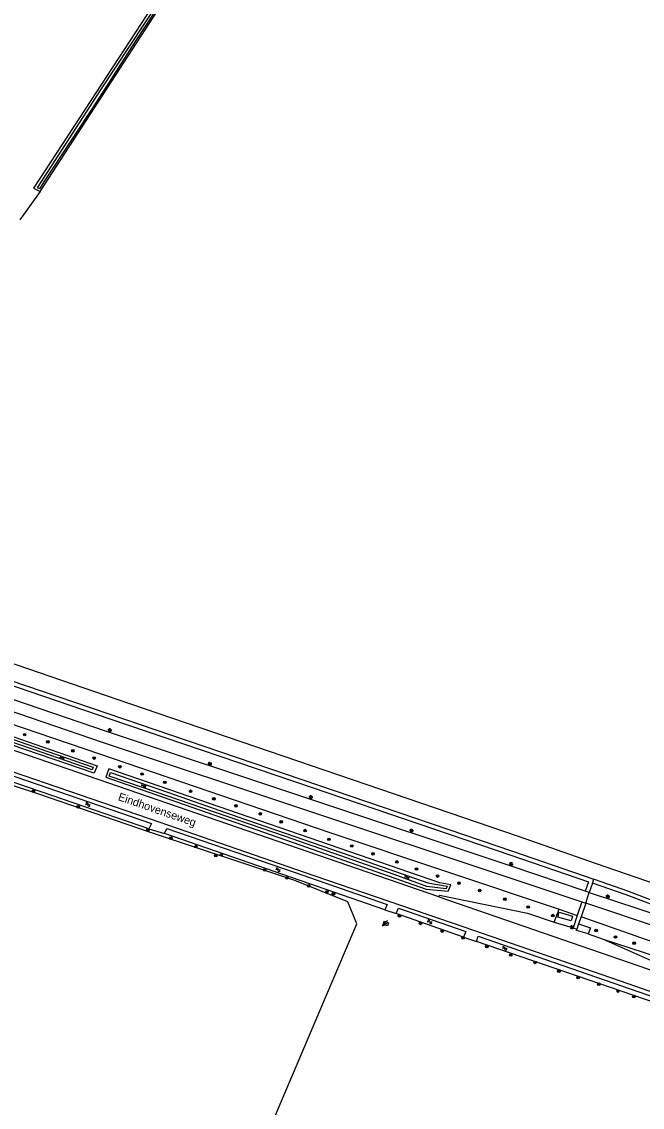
# Model space of a CAD drawing. Extents: x 135990 to 139000, y 393500 to 396000.
# Drawn here: x 136793.9 to 136987.7, y 394991 to 395330 of the extents above; entities that cross this region are included whole.
import ezdxf

# ---------------------------------------------------------------- set-up
doc = ezdxf.new("R2010")
doc.units = 0
for name, color, linetype in [('gg-afsc-faunaraster', 7, 'Continuous'), ('gg-anno-openbare ruimte label', 7, 'Continuous'), ('gg-bbg-abri', 7, 'Continuous'), ('gg-bbg-lage trafo', 7, 'Continuous'), ('gg-knt-bronhoudergrens', 7, 'Continuous'), ('gg-knt-verharding', 7, 'Continuous'), ('gg-knt-verharding nz', 7, 'Continuous'), ('gg-kntw-bovenkant insteek waterloop', 7, 'Continuous'), ('gg-kntw-waterlijn', 7, 'Continuous'), ('gt-grn-groengrens', 7, 'Continuous'), ('gt-grn-weggrens', 7, 'Continuous'), ('gt-symb-boom', 7, 'Continuous'), ('gt-symb-lichtmast', 7, 'Continuous'), ('gt-symb-trafo symbool', 7, 'Continuous'), ('gt-symb-watersymbool', 7, 'Continuous'), ('gx-grn-maaiveld', 7, 'Continuous')]:
    doc.layers.add(name, color=color, linetype=linetype)

# ---------------------------------------------------------------- blocks, each defined once
blk = doc.blocks.new('gt0-BOOM')
at = {"layer": 'gt-symb-boom'}
for radius in [0.4, 0.2]:
    blk.add_circle((0, 0), radius, dxfattribs=at)
blk = doc.blocks.new('gt0-LMAST')
at = {"layer": 'gt-symb-lichtmast'}
for p, q in [((-0.18, 0.17), (-0.45, 0.44)), ((-0.01, 0.25), (-0.01, 0.62)), ((0.17, 0.17), (0.44, 0.44)), ((-0.26, 0), (-0.63, 0)), ((-0.18, -0.18), (-0.45, -0.45)), ((-0.01, -0.25), (-0.01, -0.63)), ((0.44, -0.45), (0.17, -0.18)), ((0.24, 0), (0.62, 0))]:
    blk.add_line(p, q, dxfattribs=at)
blk.add_circle((-0.01, 0), 0.25, dxfattribs=at)
blk = doc.blocks.new('gt0-WA')
at = {"layer": 'gt-symb-watersymbool'}
for centre, start, end in [((-0.32, 0.02), 28.0725, 151.9275), ((0.43, 0.42), 208.0725, 331.9275), ((-0.32, -0.43), 28.0725, 151.9275), ((0.43, -0.03), 208.0725, 331.9275)]:
    blk.add_arc(centre, 0.425, start, end, dxfattribs=at)
blk = doc.blocks.new('gt0-HSP')
at = {"layer": 'gt-symb-trafo symbool'}
for points in [[(0.77, 0.75), (-0.53, 0), (0.47, 0), (-0.83, -0.75)], [(-0.22, -0.24), (-0.83, -0.75), (-0.08, -0.48)]]:
    blk.add_lwpolyline(points, dxfattribs=at)

msp = doc.modelspace()

# ---------------------------------------------------------------- linework, layer by layer
at = {"layer": 'gg-afsc-faunaraster'}
msp.add_lwpolyline([(136632.303, 395184.373), (136706.675, 395158.632), (136760.957, 395139.889), (136823.561, 395118.476), (136948.867, 395075.662), (136972.921, 395067.235), (136995.319, 395059.49)], dxfattribs=at)
at = {"layer": 'gg-bbg-abri'}
msp.add_lwpolyline([(136965.858, 395050.693), (136965.404, 395049.174), (136961.279, 395050.368), (136961.733, 395051.888), (136965.858, 395050.693)], dxfattribs=at)
at = {"layer": 'gg-bbg-lage trafo'}
msp.add_lwpolyline([(136907.09, 395049.068), (136908.417, 395048.605), (136908.08, 395047.639), (136906.753, 395048.102), (136907.09, 395049.068)], dxfattribs=at)
at = {"layer": 'gg-knt-bronhoudergrens'}
msp.add_line((136799.618, 395276.969), (136793.326, 395268.191), dxfattribs=at)
at = {"layer": 'gg-knt-verharding'}
for p, q in [((136972.134, 395060.996), (136971.109, 395058.053)), ((136924.147, 395056.706), (137012.655, 395026.169)), ((136960.175, 395048.76), (136961.689, 395052.865)), ((136961.689, 395052.865), (136967.364, 395050.891)), ((136968.823, 395055.089), (136967.364, 395050.891)), ((136970.056, 395054.698), (136968.573, 395050.468)), ((136967.364, 395050.891), (136966.032, 395047.06)), ((136968.573, 395050.468), (136967.738, 395048.295)), ((136966.032, 395047.06), (136967.227, 395046.629)), ((136967.738, 395048.295), (136967.227, 395046.629)), ((136970.807, 395045.091), (136975.455, 395043.512))]:
    msp.add_line(p, q, dxfattribs=at)
for points in [[(136724.247, 395146.727), (136947.105, 395070.926), (136972.554, 395062.218)], [(136725.309, 395145.037), (136758.782, 395133.671), (136821.432, 395112.332), (136884.552, 395090.872), (136946.608, 395069.724), (136970.887, 395061.4), (136969.878, 395058.479)], [(136969.878, 395058.479), (136946.693, 395066.249), (136883.58, 395087.351), (136820.389, 395108.318), (136757.753, 395129.696), (136724.034, 395141.283)], [(136725.005, 395137.127), (136819.266, 395104.948), (136882.523, 395083.915), (136945.662, 395062.844), (136968.823, 395055.089)], [(136924.147, 395056.706), (136886.334, 395069.682), (136789.614, 395103.003), (136728.373, 395124.272)], [(136726.14, 395118.098), (136787.27, 395097.063), (136837.024, 395079.972), (136885.124, 395063.406), (136931.921, 395047.31), (136980.708, 395030.491), (137010.641, 395020.085), (137020.133, 395016.766), (137027.471, 395014.486), (137030.652, 395013.873)], [(136972.554, 395062.218), (136972.603, 395062.201), (136983.062, 395058.544), (136991.512, 395055.298), (136998.208, 395052.756)], [(136997.616, 395051.522), (136991.144, 395054.108), (136982.602, 395057.304), (136972.134, 395060.996)], [(136924.147, 395056.706), (136924.327, 395057.249), (136951.786, 395051.628), (136960.175, 395048.76)], [(136971.109, 395058.053), (136994.531, 395050.331), (137002.721, 395048.173)], [(137000.991, 395044.771), (136993.669, 395046.792), (136970.056, 395054.698)], [(136967.738, 395048.295), (136971.533, 395047.017), (136970.807, 395045.091)], [(136975.455, 395043.512), (137012.973, 395026.829), (137012.655, 395026.169)]]:
    msp.add_lwpolyline(points, dxfattribs=at)
at = {"layer": 'gg-knt-verharding nz'}
for p, q in [((136971.109, 395058.053), (136969.878, 395058.479)), ((136968.823, 395055.089), (136970.056, 395054.698)), ((136960.175, 395048.76), (136966.032, 395047.06))]:
    msp.add_line(p, q, dxfattribs=at)
msp.add_lwpolyline([(136970.807, 395045.091), (136967.103, 395046.226), (136967.227, 395046.629)], dxfattribs=at)
at = {"layer": 'gg-kntw-bovenkant insteek waterloop'}
for p, q in [((136869.134, 395387.732), (136797.555, 395278.021)), ((136797.555, 395278.021), (136799.618, 395276.969)), ((136726.407, 395129.409), (136817.4, 395097.601)), ((136833.572, 395077.924), (136723.817, 395115.572)), ((136816.468, 395095.372), (136767.855, 395111.893)), ((136817.4, 395097.601), (136816.468, 395095.372)), ((136907.302, 395052.637), (136838.503, 395076.448)), ((136931.8, 395044.072), (136910.791, 395051.478)), ((136999.298, 395020.957), (136935.857, 395042.775))]:
    msp.add_line(p, q, dxfattribs=at)
for points in [[(136769.238, 395101.985), (136834.377, 395079.64), (136833.572, 395077.924)], [(136821.066, 395096.659), (136820.132, 395094.126), (136880.731, 395072.901)], [(136927.078, 395058.44), (136927.919, 395060.413), (136924.467, 395061.033), (136821.066, 395096.659)], [(136838.503, 395076.448), (136839.222, 395078.082), (136878.955, 395064.428), (136908.018, 395054.28), (136907.302, 395052.637)], [(136880.731, 395072.901), (136920.123, 395059.104), (136927.078, 395058.44)], [(136910.791, 395051.478), (136911.549, 395053.178), (136932.531, 395045.83), (136931.8, 395044.072)], [(136935.857, 395042.775), (136936.405, 395044.4), (136999.843, 395022.391)]]:
    msp.add_lwpolyline(points, dxfattribs=at)
at = {"layer": 'gg-kntw-waterlijn'}
for points in [[(136798.743, 395278.163), (136806.37, 395289.902), (136818.615, 395308.748), (136836.859, 395336.445), (136852.606, 395360.71), (136865.146, 395380.035), (136870.056, 395387.989), (136869.874, 395388.352), (136869.371, 395388.746)], [(136724.627, 395129.105), (136752.475, 395119.402), (136802.007, 395102.143), (136816.196, 395097.2), (136815.893, 395096.332), (136797.566, 395102.718), (136750.12, 395118.841), (136724.114, 395127.679)], [(136821.579, 395095.521), (136839.372, 395089.346), (136861.69, 395081.602), (136896.307, 395069.589), (136920.722, 395061.116), (136926.696, 395060.053), (136926.379, 395059.179), (136920.389, 395059.91), (136910.127, 395063.676), (136876.273, 395075.589), (136831.874, 395090.706), (136821.209, 395094.337), (136821.579, 395095.521)]]:
    msp.add_lwpolyline(points, dxfattribs=at)
at = {"layer": 'gt-grn-groengrens'}
for p, q in [((136833.572, 395077.924), (136838.503, 395076.448)), ((136907.302, 395052.637), (136910.791, 395051.478)), ((136931.8, 395044.072), (136935.857, 395042.775))]:
    msp.add_line(p, q, dxfattribs=at)
for points in [[(136723.765, 395133.456), (136728.193, 395132.857), (136755.34, 395122.738), (136818.118, 395101.325), (136890.102, 395076.813), (136961.689, 395052.865)], [(136975.455, 395043.512), (137026.382, 395026.968), (137026.877, 395029.97), (136968.573, 395050.468)]]:
    msp.add_lwpolyline(points, dxfattribs=at)
at = {"layer": 'gt-grn-weggrens'}
for p, q in [((136972.134, 395060.996), (136972.554, 395062.218)), ((136970.056, 395054.698), (136971.109, 395058.053))]:
    msp.add_line(p, q, dxfattribs=at)
at = {"layer": 'gx-grn-maaiveld'}
msp.add_line((136799.618, 395276.969), (136871.508, 395387.719), dxfattribs=at)
for points in [[(136870.85, 395388.214), (136870.114, 395386.586), (136867.556, 395382.549), (136859.783, 395370.652), (136853.465, 395360.745), (136841.355, 395342.239), (136829.342, 395323.882), (136817.233, 395305.024), (136800.819, 395280.015), (136799.368, 395277.804), (136798.743, 395278.163)], [(136879.141, 395061.757), (136833.468, 395076.999), (136799.214, 395088.789), (136769.101, 395098.667), (136741.751, 395108.598), (136720.142, 395115.701), (136707.071, 395083.956), (136684.075, 395030.901), (136668.727, 394993.566), (136647.643, 394944.812)], [(136865.066, 394969.705), (136898.535, 395048.306), (136895.711, 395055.118), (136879.141, 395061.757)]]:
    msp.add_lwpolyline(points, dxfattribs=at)

# ---------------------------------------------------------------- block references
at = {"layer": 'gt-symb-boom'}
for p in [(136794.801, 395107.364), (136802.001, 395105.101), (136809.795, 395102.308), (136816.484, 395100.035), (136824.513, 395097.325), (136831.45, 395095.071), (136838.574, 395092.451), (136797.517, 395089.713), (136846.6, 395089.668), (136853.857, 395087.289), (136811.525, 395084.83), (136860.799, 395085.142), (136868.399, 395082.604), (136874.922, 395080.132), (136833.279, 395077.566), (136882.353, 395077.39), (136840.422, 395075.039), (136848.264, 395072.391), (136889.804, 395074.672), (136896.924, 395072.558), (136854.456, 395069.6), (136856.209, 395069.788), (136903.584, 395070.11), (136911.002, 395067.605), (136917.144, 395065.391), (136869.727, 395065.07), (136876.709, 395062.638), (136923.737, 395063.177), (136883.463, 395060.135), (136930.434, 395060.958), (136936.874, 395058.658), (136889.21, 395058.31), (136891.234, 395057.619), (136944.723, 395055.975), (136952.039, 395053.51), (136911.811, 395050.784), (136918.391, 395048.401), (136959.748, 395050.842), (136925.18, 395046.002), (136973.267, 395046.202), (136931.706, 395043.904), (136979.297, 395044.137), (136985.132, 395042.22), (136939.134, 395041.175), (136946.588, 395038.531), (136954.226, 395036.211), (136961.6, 395033.457), (136967.625, 395031.463), (136974.079, 395029.395), (136980.086, 395027.256), (136984.995, 395025.535)]:
    msp.add_blockref('gt0-BOOM', p, dxfattribs=at)
at = {"layer": 'gt-symb-lichtmast'}
for p in [(136821.372, 395108.724), (136852.647, 395098.262), (136884.174, 395087.832), (136915.581, 395077.365), (136946.7, 395066.932), (136976.869, 395056.778), (136965.717, 395047.199)]:
    msp.add_blockref('gt0-LMAST', p, dxfattribs=at)
at = {"layer": 'gt-symb-trafo symbool'}
msp.add_blockref('gt0-HSP', (136907.371, 395048.401), dxfattribs=at)
at = {"layer": 'gt-symb-watersymbool'}
for p, rotation in [((136806.38, 395100.151), -12.006708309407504), ((136831.936, 395091.457), -12.00670830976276), ((136814.479, 395085.522), -12.006708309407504), ((136873.875, 395065.183), -12.0067083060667), ((136914.1, 395062.842), -12.006708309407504), ((136921.241, 395048.901), -12.006708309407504), ((136944.667, 395040.62), -12.00670830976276)]:
    msp.add_blockref('gt0-WA', p, dxfattribs=dict(at, rotation=rotation))

# ---------------------------------------------------------------- texts
at = {"layer": 'gg-anno-openbare ruimte label'}
msp.add_text('Eindhovenseweg', height=2.5, rotation=340.9, dxfattribs=at).set_placement((136823.749, 395086.942))

doc.saveas('drawing.dxf')
